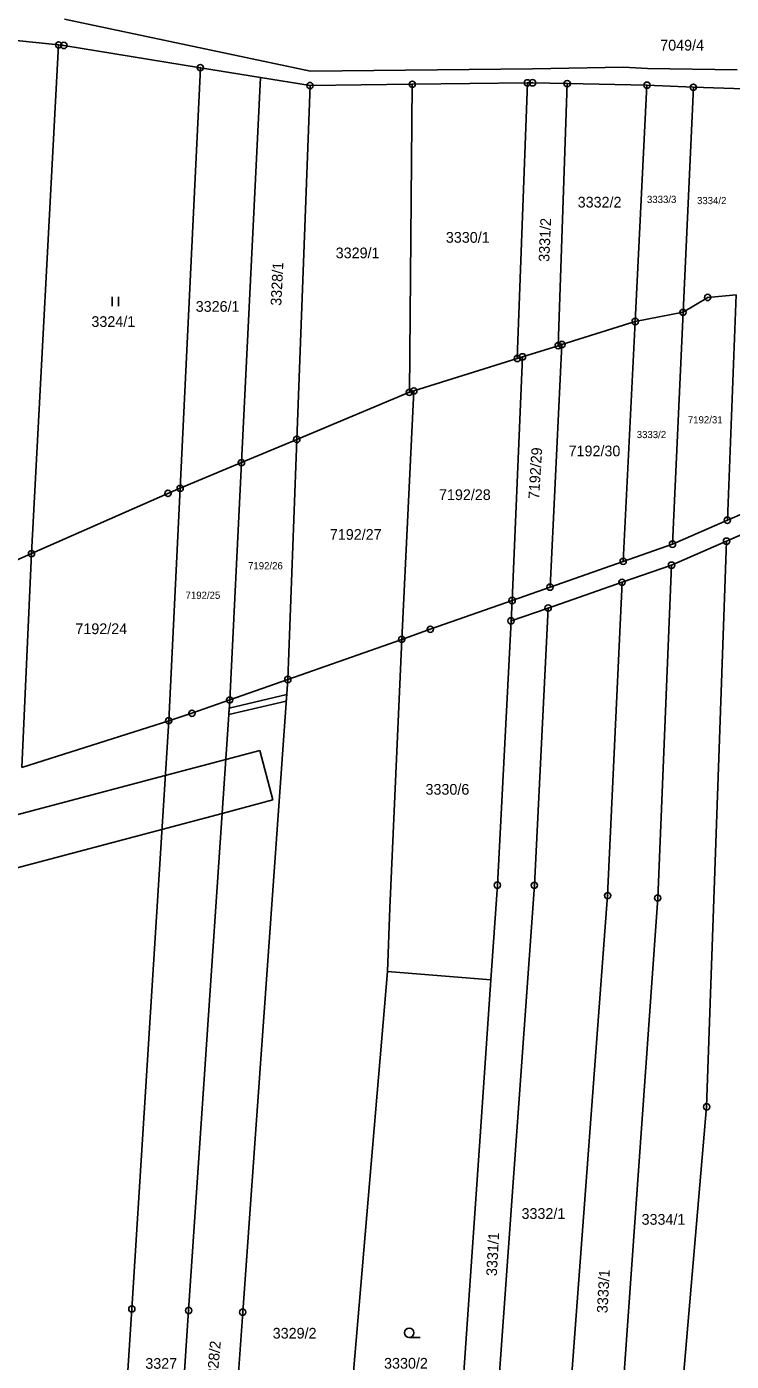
# Model space of a CAD drawing. Extents: x -593183 to -588034, y -1130415 to -1124994.
# Drawn here: x -592442.1 to -592330.3, y -1128347 to -1128135.2 of the extents above; entities that cross this region are included whole.
import ezdxf

# ---------------------------------------------------------------- set-up
doc = ezdxf.new("R2010")
doc.units = 0
for name, color, linetype in [('Vrstva 1', 7, 'Continuous'), ('Vrstva 18', 7, 'Continuous'), ('Vrstva 24', 7, 'Continuous'), ('Vrstva 25', 7, 'Continuous'), ('Vrstva 27', 7, 'Continuous'), ('Vrstva 4', 7, 'Continuous')]:
    doc.layers.add(name, color=color, linetype=linetype)

msp = doc.modelspace()

# ---------------------------------------------------------------- linework, layer by layer
at = {"layer": 'Vrstva 1'}
for p, q in [((-592457.77, -1128135.99), (-592437.06, -1128138.09)), ((-592437.06, -1128138.09), (-592441.36, -1128218.84)), ((-592436.23, -1128138.17), (-592437.06, -1128138.09)), ((-592436.23, -1128138.17), (-592414.56, -1128141.7)), ((-592414.56, -1128141.7), (-592417.77, -1128208.46)), ((-592414.56, -1128141.7), (-592405.03, -1128143.26)), ((-592405.03, -1128143.26), (-592408.04, -1128204.39)), ((-592405.03, -1128143.26), (-592397.16, -1128144.54)), ((-592397.16, -1128144.54), (-592399.26, -1128200.71)), ((-592397.16, -1128144.54), (-592380.93, -1128144.33)), ((-592380.93, -1128144.33), (-592381.39, -1128193.23)), ((-592380.93, -1128144.33), (-592362.66, -1128144.11)), ((-592362.66, -1128144.11), (-592364.26, -1128187.86)), ((-592362.66, -1128144.11), (-592361.84, -1128144.1)), ((-592361.84, -1128144.1), (-592356.34, -1128144.23)), ((-592356.34, -1128144.23), (-592357.77, -1128185.83)), ((-592356.34, -1128144.23), (-592343.68, -1128144.48)), ((-592343.68, -1128144.48), (-592345.55, -1128181.99)), ((-592343.68, -1128144.48), (-592336.32, -1128144.81)), ((-592336.32, -1128144.81), (-592337.95, -1128180.53)), ((-592336.32, -1128144.81), (-592328.3, -1128145.08)), ((-592334.04, -1128178.17), (-592329.54, -1128177.76)), ((-592329.54, -1128177.76), (-592330.92, -1128213.53)), ((-592337.95, -1128180.53), (-592334.04, -1128178.17)), ((-592357.19, -1128185.65), (-592345.55, -1128181.99)), ((-592347.46, -1128220.07), (-592345.55, -1128181.99)), ((-592345.55, -1128181.99), (-592337.95, -1128180.53)), ((-592337.95, -1128180.53), (-592339.63, -1128217.34)), ((-592363.44, -1128187.6), (-592357.77, -1128185.83)), ((-592357.19, -1128185.65), (-592359.07, -1128224.16)), ((-592357.77, -1128185.83), (-592357.19, -1128185.65)), ((-592380.69, -1128193.01), (-592364.26, -1128187.86)), ((-592363.44, -1128187.6), (-592365.08, -1128226.27)), ((-592364.26, -1128187.86), (-592363.44, -1128187.6)), ((-592399.26, -1128200.71), (-592381.39, -1128193.23)), ((-592380.69, -1128193.01), (-592382.6, -1128232.44)), ((-592381.39, -1128193.23), (-592380.69, -1128193.01)), ((-592408.04, -1128204.39), (-592399.26, -1128200.71)), ((-592399.26, -1128200.71), (-592400.68, -1128238.81)), ((-592417.77, -1128208.46), (-592408.04, -1128204.39)), ((-592408.04, -1128204.39), (-592409.9, -1128242.06)), ((-592330.92, -1128213.53), (-592312.1, -1128205.31)), ((-592441.36, -1128218.84), (-592419.71, -1128209.27)), ((-592419.71, -1128209.27), (-592417.77, -1128208.46)), ((-592417.77, -1128208.46), (-592419.59, -1128245.35)), ((-592331.05, -1128216.86), (-592309.78, -1128207.57)), ((-592339.63, -1128217.34), (-592330.92, -1128213.53)), ((-592347.46, -1128220.07), (-592339.63, -1128217.34)), ((-592339.78, -1128220.67), (-592331.05, -1128216.86)), ((-592331.05, -1128216.86), (-592334.21, -1128306.65)), ((-592443.83, -1128219.93), (-592441.36, -1128218.84)), ((-592441.36, -1128218.84), (-592442.89, -1128252.77)), ((-592359.07, -1128224.16), (-592347.46, -1128220.07)), ((-592347.63, -1128223.39), (-592339.78, -1128220.67)), ((-592339.78, -1128220.67), (-592341.97, -1128273.51)), ((-592365.08, -1128226.27), (-592359.07, -1128224.16)), ((-592359.37, -1128227.47), (-592347.63, -1128223.39)), ((-592347.63, -1128223.39), (-592349.93, -1128273.12)), ((-592378.07, -1128230.84), (-592365.08, -1128226.27)), ((-592365.08, -1128226.27), (-592365.25, -1128229.51)), ((-592365.25, -1128229.51), (-592359.37, -1128227.47)), ((-592359.37, -1128227.47), (-592361.55, -1128271.48)), ((-592365.25, -1128229.51), (-592367.42, -1128271.46)), ((-592400.68, -1128238.81), (-592382.6, -1128232.44)), ((-592382.6, -1128232.44), (-592384.51, -1128275.1)), ((-592382.6, -1128232.44), (-592378.07, -1128230.84)), ((-592409.9, -1128242.06), (-592400.68, -1128238.81)), ((-592400.68, -1128238.81), (-592407.84, -1128339.23)), ((-592409.9, -1128242.06), (-592416.42, -1128338.98)), ((-592415.9, -1128244.17), (-592409.9, -1128242.06)), ((-592442.89, -1128252.77), (-592419.59, -1128245.35)), ((-592419.59, -1128245.35), (-592425.44, -1128338.73)), ((-592419.59, -1128245.35), (-592415.9, -1128244.17)), ((-592361.55, -1128271.48), (-592372.37, -1128422.32)), ((-592367.42, -1128271.46), (-592368.44, -1128286.46)), ((-592349.93, -1128273.12), (-592361.14, -1128422.47)), ((-592384.51, -1128275.1), (-592384.86, -1128285.14)), ((-592341.97, -1128273.51), (-592352.48, -1128422.59)), ((-592384.86, -1128285.14), (-592393.8, -1128390.13)), ((-592384.86, -1128285.14), (-592368.44, -1128286.46)), ((-592368.44, -1128286.46), (-592370.08, -1128310.56)), ((-592334.21, -1128306.65), (-592343.73, -1128417.73)), ((-592370.08, -1128310.56), (-592373.76, -1128363.68)), ((-592425.44, -1128338.73), (-592431.29, -1128432.06)), ((-592416.42, -1128338.98), (-592422.59, -1128430.59)), ((-592407.84, -1128339.23), (-592414.19, -1128428.23))]:
    msp.add_line(p, q, dxfattribs=at)
at = {"layer": 'Vrstva 24'}
for centre, radius in [((-592437.06, -1128138.09), 0.5), ((-592437.06, -1128138.09), 0.0327), ((-592436.23, -1128138.17), 0.5), ((-592436.23, -1128138.17), 0.0327), ((-592414.56, -1128141.7), 0.5), ((-592414.56, -1128141.7), 0.0327), ((-592380.93, -1128144.33), 0.5), ((-592362.66, -1128144.11), 0.5), ((-592361.84, -1128144.1), 0.5), ((-592356.34, -1128144.23), 0.5), ((-592397.16, -1128144.54), 0.5), ((-592397.16, -1128144.54), 0.0327), ((-592380.93, -1128144.33), 0.0327), ((-592362.66, -1128144.11), 0.0327), ((-592361.84, -1128144.1), 0.0327), ((-592356.34, -1128144.23), 0.0327), ((-592343.68, -1128144.48), 0.5), ((-592343.68, -1128144.48), 0.0327), ((-592336.32, -1128144.81), 0.5), ((-592336.32, -1128144.81), 0.0327), ((-592334.04, -1128178.17), 0.5), ((-592334.04, -1128178.17), 0.0327), ((-592345.55, -1128181.99), 0.5), ((-592345.55, -1128181.99), 0.0327), ((-592337.95, -1128180.53), 0.5), ((-592337.95, -1128180.53), 0.0327), ((-592357.77, -1128185.83), 0.5), ((-592357.77, -1128185.83), 0.0327), ((-592357.19, -1128185.65), 0.5), ((-592357.19, -1128185.65), 0.0327), ((-592364.26, -1128187.86), 0.5), ((-592364.26, -1128187.86), 0.0327), ((-592363.44, -1128187.6), 0.5), ((-592363.44, -1128187.6), 0.0327), ((-592380.69, -1128193.01), 0.5), ((-592381.39, -1128193.23), 0.5), ((-592381.39, -1128193.23), 0.0327), ((-592380.69, -1128193.01), 0.0327), ((-592399.26, -1128200.71), 0.5), ((-592399.26, -1128200.71), 0.0327), ((-592408.04, -1128204.39), 0.5), ((-592408.04, -1128204.39), 0.0327), ((-592419.71, -1128209.27), 0.5), ((-592419.71, -1128209.27), 0.0327), ((-592417.77, -1128208.46), 0.5), ((-592417.77, -1128208.46), 0.0327), ((-592330.92, -1128213.53), 0.5), ((-592330.92, -1128213.53), 0.0327), ((-592339.63, -1128217.34), 0.5), ((-592339.63, -1128217.34), 0.0327), ((-592331.05, -1128216.86), 0.5), ((-592331.05, -1128216.86), 0.0327), ((-592441.36, -1128218.84), 0.5), ((-592441.36, -1128218.84), 0.0327), ((-592347.46, -1128220.07), 0.5), ((-592347.46, -1128220.07), 0.0327), ((-592339.78, -1128220.67), 0.5), ((-592339.78, -1128220.67), 0.0327), ((-592359.07, -1128224.16), 0.5), ((-592359.07, -1128224.16), 0.0327), ((-592347.63, -1128223.39), 0.5), ((-592347.63, -1128223.39), 0.0327), ((-592365.08, -1128226.27), 0.5), ((-592365.08, -1128226.27), 0.0327), ((-592359.37, -1128227.47), 0.5), ((-592359.37, -1128227.47), 0.0327), ((-592378.07, -1128230.84), 0.5), ((-592365.25, -1128229.51), 0.5), ((-592365.25, -1128229.51), 0.0327), ((-592382.6, -1128232.44), 0.5), ((-592382.6, -1128232.44), 0.0327), ((-592378.07, -1128230.84), 0.0327), ((-592400.68, -1128238.81), 0.5), ((-592400.68, -1128238.81), 0.0327), ((-592409.9, -1128242.06), 0.5), ((-592409.9, -1128242.06), 0.0327), ((-592419.59, -1128245.35), 0.5), ((-592419.59, -1128245.35), 0.0327), ((-592415.9, -1128244.17), 0.5), ((-592415.9, -1128244.17), 0.0327), ((-592367.42, -1128271.46), 0.5), ((-592361.55, -1128271.48), 0.5), ((-592367.42, -1128271.46), 0.0327), ((-592361.55, -1128271.48), 0.0327), ((-592349.93, -1128273.12), 0.5), ((-592349.93, -1128273.12), 0.0327), ((-592341.97, -1128273.51), 0.5), ((-592341.97, -1128273.51), 0.0327), ((-592334.21, -1128306.65), 0.5), ((-592334.21, -1128306.65), 0.0327), ((-592425.44, -1128338.73), 0.5), ((-592425.44, -1128338.73), 0.0327), ((-592416.42, -1128338.98), 0.5), ((-592407.84, -1128339.23), 0.5), ((-592416.42, -1128338.98), 0.0327), ((-592407.84, -1128339.23), 0.0327)]:
    msp.add_circle(centre, radius, dxfattribs=at)
at = {"layer": 'Vrstva 25'}
for p, q in [((-592428.57, -1128178.07), (-592428.57, -1128179.57)), ((-592427.55, -1128179.57), (-592427.55, -1128178.07)), ((-592379.67, -1128343.26), (-592381.42, -1128343.26))]:
    msp.add_line(p, q, dxfattribs=at)
msp.add_circle((-592381.42, -1128342.51), 0.75, dxfattribs=at)
at = {"layer": 'Vrstva 27'}
for p, q in [((-592409.99, -1128243.35), (-592400.85, -1128241.22)), ((-592400.85, -1128241.22), (-592400.93, -1128242.26)), ((-592400.93, -1128242.26), (-592410.06, -1128244.39)), ((-592410.06, -1128244.39), (-592409.99, -1128243.35)), ((-592420.13, -1128254.04), (-592410.54, -1128251.5)), ((-592410.54, -1128251.5), (-592405.14, -1128250.07)), ((-592405.14, -1128250.07), (-592403.05, -1128257.94)), ((-592444.92, -1128260.61), (-592420.13, -1128254.04)), ((-592403.05, -1128257.94), (-592411.11, -1128260.08)), ((-592411.11, -1128260.08), (-592420.67, -1128262.61)), ((-592420.67, -1128262.61), (-592445.45, -1128269.18))]:
    msp.add_line(p, q, dxfattribs=at)
at = {"layer": 'Vrstva 4'}
for p, q in [((-592436.14, -1128134.01), (-592397.09, -1128142.25)), ((-592361.83, -1128141.86), (-592347.41, -1128141.6)), ((-592347.41, -1128141.6), (-592343.6, -1128141.82)), ((-592397.09, -1128142.25), (-592361.83, -1128141.86)), ((-592343.6, -1128141.82), (-592329.39, -1128142.02))]:
    msp.add_line(p, q, dxfattribs=at)

# ---------------------------------------------------------------- texts
at = {"layer": 'Vrstva 18'}
for s, height, p in [('7049/4', 1.7, (-592341.58, -1128138.98)), ('3332/2', 1.7, (-592354.68, -1128163.9)), ('3333/3', 1.14, (-592343.68, -1128163.18)), ('3334/2', 1.14, (-592335.74, -1128163.36)), ('3330/1', 1.7, (-592375.6, -1128169.49)), ('3329/1', 1.7, (-592393.08, -1128171.95)), ('3326/1', 1.7, (-592415.3, -1128180.45)), ('3324/1', 1.7, (-592431.85, -1128182.85)), ('7192/31', 1.14, (-592337.19, -1128198.16)), ('3333/2', 1.14, (-592345.3, -1128200.5)), ('7192/30', 1.7, (-592356.12, -1128203.39)), ('7192/28', 1.7, (-592376.69, -1128210.33)), ('7192/27', 1.7, (-592394.01, -1128216.64)), ('7192/26', 1.14, (-592406.99, -1128221.33)), ('7192/25', 1.14, (-592416.91, -1128226.01)), ('7192/24', 1.7, (-592434.4, -1128231.61)), ('3330/6', 1.7, (-592378.83, -1128257.1)), ('3332/1', 1.7, (-592363.59, -1128324.43)), ('3334/1', 1.7, (-592344.54, -1128325.36)), ('3329/2', 1.7, (-592403.08, -1128343.43)), ('3327', 1.7, (-592423.3, -1128348.23)), ('3330/2', 1.7, (-592385.41, -1128348.2))]:
    msp.add_text(s, height=height, dxfattribs=at).set_placement(p)
for s, rotation, p in [('3331/2', 87.5165, (-592359.19, -1128172.55)), ('3328/1', 87.1963, (-592401.72, -1128179.52)), ('7192/29', 86.4299, (-592360.81, -1128210.24)), ('3331/1', 86.9147, (-592367.51, -1128333.54)), ('3333/1', 86.8749, (-592349.95, -1128339.43)), ('3328/2', 84.785, (-592411.94, -1128350.79))]:
    msp.add_text(s, height=1.7, rotation=rotation, dxfattribs=at).set_placement(p)

doc.saveas('drawing.dxf')
